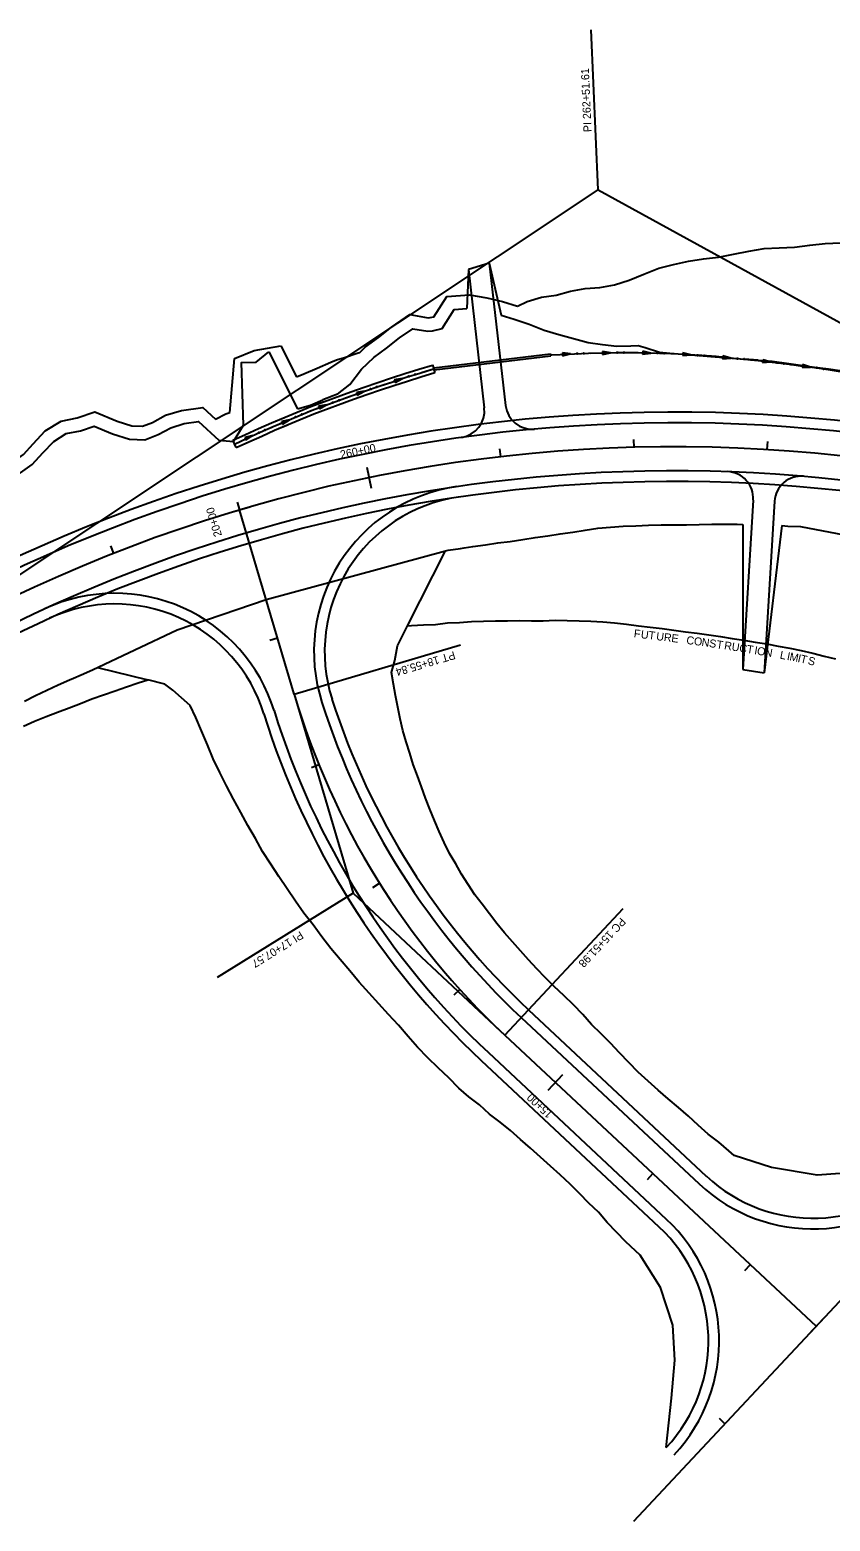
# Model space of a CAD drawing. Extents: x 979959 to 994833, y 1835619 to 1845316.
# Drawn here: x 991264 to 991864, y 1838829 to 1839947 of the extents above; entities that cross this region are included whole.
import ezdxf

# ---------------------------------------------------------------- set-up
doc = ezdxf.new("R2010")
doc.units = 0
for name, color, linetype in [('Future 5 Lane Construction Limits', 7, 'Continuous'), ('R_CONCRETE', 7, 'Continuous'), ('R_Drainage', 7, 'Continuous'), ('R_Horz Alg', 7, 'Continuous'), ('R_Horz Alg Annot', 7, 'Continuous'), ('R_Horz Alg Annot_Side Road', 7, 'Continuous'), ('R_Horz Alg Stationing', 7, 'Continuous'), ('R_Proposed Const Limits', 7, 'Continuous'), ('R_Proposed Road', 7, 'Continuous'), ('R_Proposed Road Future', 7, 'Continuous'), ('R_Special Ditch', 7, 'Continuous')]:
    doc.layers.add(name, color=color, linetype=linetype)

msp = doc.modelspace()

# ---------------------------------------------------------------- linework, layer by layer
msp.add_line((991747.4, 1839704.5), (991781.4, 1839701.9))
for points in [[(991654.7, 1839703.5), (991661.9, 1839703.9), (991672.6, 1839704.4), (991683.2, 1839704.7), (991693.8, 1839705), (991704.4, 1839705.2), (991715.1, 1839705.3), (991720.4, 1839705.3), (991725.7, 1839705.1), (991736.3, 1839704.7), (991746.6, 1839704.6)], [(991781.4, 1839701.9), (991799.7, 1839700.3), (991810.4, 1839699.2)], [(991810.4, 1839699.2), (991820.9, 1839698), (991831.4, 1839696.8), (991835.3, 1839696.3), (991841.9, 1839695.4), (991852.4, 1839694), (991862.8, 1839692.5), (991873.3, 1839690.9), (991883.7, 1839689.2), (991894.1, 1839687.4), (991904.5, 1839685.5), (991910.4, 1839684.4)]]:
    msp.add_lwpolyline(points)
at = {"layer": 'Future 5 Lane Construction Limits'}
for p, q in [((991452.4, 1839710.2), (991464.1, 1839687)), ((991414.3, 1839660.4), (991417.8, 1839700.7))]:
    msp.add_line(p, q, dxfattribs=at)
for points in [[(991630, 1839739.9), (991637.1, 1839743.6), (991647.9, 1839746.7), (991658.8, 1839748.3), (991669.7, 1839751.2), (991680.6, 1839753.3), (991691.7, 1839754.1), (991702.6, 1839755.9), (991713.6, 1839759.4), (991724.6, 1839764), (991735.7, 1839768.4), (991746.9, 1839771.3), (991758.1, 1839773.7), (991769.3, 1839775.4), (991780.6, 1839776.8), (991791.9, 1839779), (991803.3, 1839781.3), (991814.7, 1839783.3), (991826.1, 1839783.7), (991837.5, 1839784.2), (991849, 1839785.7), (991860.5, 1839786.9), (991871.9, 1839787.4)], [(991511.7, 1839705.4), (991515.8, 1839709.2), (991525.7, 1839716.5), (991535.5, 1839724.4), (991549.1, 1839733.7), (991563, 1839731.3), (991564.3, 1839731.4), (991567.1, 1839732.1), (991576.8, 1839747.3), (991594, 1839748.4), (991606.8, 1839746.2), (991618.7, 1839743.4), (991630, 1839739.9)], [(991417.8, 1839700.7), (991432.6, 1839706.9), (991452.4, 1839710.2)], [(991464.1, 1839687), (991469.8, 1839689.2), (991479.8, 1839693.5), (991489.9, 1839698), (991494.2, 1839699.8), (991500.1, 1839701.6), (991510.5, 1839705), (991511.7, 1839705.4)], [(991229, 1839623.7), (991232.5, 1839624.1), (991244.6, 1839626.1), (991254.4, 1839625.2), (991259.5, 1839628.9), (991266.8, 1839636.9), (991275.9, 1839646.5), (991287.9, 1839653.9), (991299.8, 1839656.2), (991313, 1839660.8), (991329.7, 1839653.8), (991340.8, 1839650.4), (991348.8, 1839650), (991356.2, 1839652.9), (991366.1, 1839658.2), (991378, 1839661.8), (991394.1, 1839664), (991403.5, 1839655.4)], [(991403.5, 1839655.4), (991411.3, 1839659.2), (991414.3, 1839660.4)], [(991547.4, 1839500.4), (991550.3, 1839500.6), (991559.4, 1839501.1), (991568.4, 1839501.5), (991577.3, 1839502.6), (991586.3, 1839503), (991595.3, 1839503.7), (991604.3, 1839504), (991613.3, 1839504.2), (991622.3, 1839504.2), (991631.3, 1839504.3), (991640.3, 1839504.1), (991649.2, 1839504.1), (991658.1, 1839504.6), (991667.1, 1839504.5), (991676, 1839504.2), (991684.9, 1839503.9), (991693.8, 1839503.4), (991702.7, 1839502.6), (991711.6, 1839501.6), (991720.5, 1839500.5), (991729.4, 1839499.4), (991738.2, 1839498.3), (991747, 1839497.2), (991755.8, 1839496), (991764.6, 1839494.9), (991773.3, 1839493.6), (991782.1, 1839492.3), (991790.8, 1839491), (991799.5, 1839489.7), (991808.1, 1839488.2), (991816.8, 1839486.8), (991825.4, 1839485.2), (991834.1, 1839483.6), (991842.6, 1839481.9), (991851.2, 1839479.9), (991859.7, 1839477.8), (991868.2, 1839475.7)], [(991259.5, 1839425.2), (991267.9, 1839428.9), (991271.5, 1839430.4), (991276.5, 1839432.4), (991285.1, 1839435.7), (991293.7, 1839439), (991302.4, 1839442.1), (991310.8, 1839445.8), (991319.5, 1839448.8), (991328.2, 1839451.8), (991336.8, 1839454.7), (991336.9, 1839454.8), (991345.6, 1839457.6), (991352.8, 1839460)]]:
    msp.add_lwpolyline(points, dxfattribs=at)
at = {"layer": 'R_CONCRETE'}
for p, q in [((991567.3, 1839693.1), (991566.5, 1839696)), ((991568.2, 1839690.3), (991567.5, 1839692.4)), ((991419, 1839634), (991416.5, 1839639.5))]:
    msp.add_line(p, q, dxfattribs=at)
for points in [[(991474.9, 1839664.9), (991505, 1839675.9), (991515, 1839679.4), (991525.2, 1839682.9), (991535.3, 1839686.3), (991545.5, 1839689.6), (991555.8, 1839692.8), (991566.1, 1839695.9), (991566.5, 1839696)], [(991477.1, 1839659.3), (991507, 1839670.2), (991517, 1839673.8), (991527.1, 1839677.2), (991537.2, 1839680.6), (991547.3, 1839683.9), (991557.5, 1839687), (991567.8, 1839690.2), (991568.2, 1839690.3)], [(991416.5, 1839639.5), (991426.1, 1839643.9), (991435.7, 1839648.2), (991445.5, 1839652.5), (991474.9, 1839664.9)], [(991419, 1839634), (991428.6, 1839638.4), (991438.2, 1839642.7), (991447.8, 1839647), (991477.1, 1839659.3)], [(991426.1, 1839643.9), (991435.7, 1839648.2), (991445.5, 1839652.5), (991455.2, 1839656.6)], [(991428.5, 1839638.4), (991438.2, 1839642.7), (991447.8, 1839647), (991457.6, 1839651.1)]]:
    msp.add_lwpolyline(points, dxfattribs=at)
at = {"layer": 'R_Drainage'}
for p, q in [((991567.2, 1839693.9), (991654.6, 1839704.3)), ((991567.4, 1839692.4), (991654.8, 1839702.8)), ((991654.6, 1839704.3), (991654.8, 1839702.8)), ((991567.2, 1839693.9), (991567.4, 1839692.4))]:
    msp.add_line(p, q, dxfattribs=at)
at = {"layer": 'R_Horz Alg'}
for p, q in [((991462.5, 1839449.1), (991421.5, 1839587.3)), ((991717.1, 1838829.3), (992201.2, 1839346.9))]:
    msp.add_line(p, q, dxfattribs=at)
msp.add_lwpolyline([(991620.4, 1839193.7), (991853.7, 1838975.4)], dxfattribs=at)
for centre, radius, start, end in [((991747.5, 1838488.7), 1145.9, 61.242, 123.6492), ((992011.8, 1839612.1), 573, 196.5251, 226.9104)]:
    msp.add_arc(centre, radius, start, end, dxfattribs=at)
at = {"layer": 'R_Horz Alg Annot'}
for points in [[(991690.3, 1839827.3), (991685.2, 1839947.1)], [(991462.5, 1839449.1), (991587.1, 1839486.1)], [(991506.8, 1839300), (991404.7, 1839236.9)], [(991620.4, 1839193.7), (991709.2, 1839288.6)]]:
    msp.add_lwpolyline(points, dxfattribs=at)
at = {"layer": 'R_Horz Alg Annot_Side Road'}
for p, q in [((991112.5, 1839442.7), (991690.3, 1839827.3)), ((991690.3, 1839827.3), (992298.8, 1839493.3)), ((991462.5, 1839449.1), (991506.8, 1839300)), ((991506.8, 1839300), (991620.4, 1839193.7))]:
    msp.add_line(p, q, dxfattribs=at)
at = {"layer": 'R_Horz Alg Stationing'}
for points in [[(991716.8, 1839640.2), (991717, 1839634.2)], [(991616.5, 1839633.2), (991617.2, 1839627.2)], [(991817.3, 1839638.5), (991816.9, 1839632.5)], [(991516.9, 1839619.4), (991520.1, 1839603.7)], [(991413.8, 1839585), (991429.2, 1839589.6)], [(991419.8, 1839593.1), (991421.5, 1839587.3)], [(991324.8, 1839560.3), (991327, 1839554.7)], [(991444.2, 1839489.7), (991450, 1839491.5)], [(991475.4, 1839394.2), (991481, 1839396.4)], [(991521.4, 1839304.4), (991526.5, 1839307.5)], [(991582.3, 1839223.9), (991586.7, 1839227.9)], [(991652.9, 1839152.3), (991663.8, 1839164)], [(991727.3, 1839085.5), (991731.4, 1839089.8)], [(991800.3, 1839017.1), (991804.4, 1839021.5)], [(991848.3, 1838969.5), (991859.2, 1838981.2)], [(991849.4, 1838979.5), (991853.7, 1838975.4)], [(991781, 1838906.5), (991785.4, 1838902.4)]]:
    msp.add_lwpolyline(points, dxfattribs=at)
at = {"layer": 'R_Proposed Const Limits'}
for p, q in [((991593.1, 1839767.6), (991592, 1839738.3)), ((991608.7, 1839772.3), (991617.6, 1839733.3)), ((991443.5, 1839705.7), (991465, 1839663)), ((991736.3, 1839705.6), (991746.9, 1839704.6)), ((991810.4, 1839699.5), (991799.8, 1839700.4)), ((991494.9, 1839674.1), (991484, 1839669.7)), ((991406, 1839639.5), (991417.1, 1839638.7)), ((991798.8, 1839576.4), (991798.9, 1839467.6)), ((991828.1, 1839575.5), (991814.8, 1839465.3))]:
    msp.add_line(p, q, dxfattribs=at)
for points in [[(991494.9, 1839674.1), (991504.3, 1839681.3), (991512.9, 1839692.8), (991522.1, 1839701.5), (991531.8, 1839708.5), (991541.5, 1839716.3), (991551.4, 1839723.1), (991562.7, 1839721.2), (991566.1, 1839721.6), (991573.4, 1839723.3), (991582.5, 1839737.6), (991592, 1839738.3)], [(991617.6, 1839733.3), (991627.4, 1839730.3), (991638.6, 1839726.4), (991649.8, 1839722.1), (991660.9, 1839718.9), (991671.9, 1839715.8), (991682.8, 1839712.9), (991693.5, 1839711.2), (991704.3, 1839710.1), (991714.9, 1839710.4), (991720.3, 1839710.5), (991725.6, 1839709), (991736.3, 1839705.6)], [(991417.1, 1839638.7), (991424.6, 1839650.8), (991422.9, 1839697.9), (991434.1, 1839698.1), (991443.5, 1839705.7)], [(991746.9, 1839704.6), (991757.5, 1839703.9), (991768.1, 1839703.3), (991778.7, 1839702.5), (991789.3, 1839701.4), (991799.8, 1839700.4)], [(991810.4, 1839699.5), (991820.9, 1839698.7), (991831.4, 1839697.3), (991841.9, 1839695.9), (991852.4, 1839694.3), (991862.9, 1839693), (991873.3, 1839691.5), (991883.8, 1839690.2), (991894.3, 1839689.1), (991904.7, 1839687.6), (991910.8, 1839686.4)], [(991465, 1839663), (991474.8, 1839665.7), (991484, 1839669.7)], [(991220.4, 1839605.2), (991223.8, 1839610.3), (991226.5, 1839613.2), (991233.9, 1839614.2), (991245, 1839616), (991257.2, 1839615), (991266.1, 1839621.3), (991274.1, 1839630), (991282.3, 1839638.6), (991291.6, 1839644.5), (991302.4, 1839646.5), (991312.6, 1839650.1), (991326.3, 1839644.4), (991339, 1839640.4), (991350.5, 1839639.9), (991360.4, 1839643.8), (991369.9, 1839648.9), (991380.1, 1839652), (991390.8, 1839653.5), (991406, 1839639.5)], [(991576, 1839556.7), (991577.8, 1839557.1), (991587.1, 1839558.5), (991590, 1839558.9), (991596.4, 1839559.8), (991605.8, 1839561.1), (991615.1, 1839562.7), (991624.5, 1839563.6), (991633.8, 1839565.1), (991643.2, 1839566.7), (991652.6, 1839567.9), (991661.9, 1839569.4), (991671.3, 1839570.6), (991680.7, 1839572.1), (991690.1, 1839573.5), (991699.6, 1839574.4), (991709, 1839575), (991718.5, 1839575.4), (991723.3, 1839575.6), (991728, 1839575.8), (991737.5, 1839576), (991747, 1839576.1), (991756.5, 1839576.2), (991766, 1839576.4), (991775.5, 1839576.6), (991785, 1839576.6), (991794.5, 1839576.5), (991798.8, 1839576.4)], [(991828.1, 1839575.5), (991832.5, 1839575.2), (991842, 1839574.8), (991907.5, 1839562.5), (992012.3, 1839552.8), (992021.6, 1839550.6), (992030.8, 1839548.2), (992040.2, 1839546.2)], [(991374.8, 1839497.3), (991441.4, 1839520.2), (991576, 1839556.7)], [(991547.4, 1839500.4), (991576, 1839556.7)], [(991260.2, 1839443.9), (991268.6, 1839448.2), (991277, 1839452.1), (991285.5, 1839456.2), (991294.1, 1839459.9), (991297, 1839461.1), (991302.7, 1839463.6), (991311.2, 1839467.5), (991374.8, 1839497.3)], [(991535.4, 1839465.4), (991537.8, 1839474.4), (991539.8, 1839485.4), (991547.4, 1839500.4)], [(991315, 1839469.3), (991352.8, 1839460)], [(991720.4, 1839165.9), (991713.3, 1839173), (991706.4, 1839180.3), (991699.5, 1839187.5), (991692.5, 1839194.6), (991685.3, 1839201.6), (991678.8, 1839209.2), (991671.8, 1839216.4), (991664.6, 1839223.4), (991657.3, 1839230.2), (991650.7, 1839236.8), (991644.4, 1839243.3), (991638.2, 1839250), (991632.1, 1839256.7), (991626.2, 1839263.6), (991620.2, 1839270.4), (991614.5, 1839277.4), (991609, 1839284.6), (991603.5, 1839291.8), (991597.9, 1839298.9), (991592.9, 1839306.5), (991588, 1839314.2), (991583.6, 1839322), (991578.9, 1839329.8), (991575, 1839338), (991571.2, 1839346.2), (991567.6, 1839354.5), (991564.2, 1839362.9), (991561, 1839371.3), (991558, 1839379.8), (991554.9, 1839388.1), (991551.7, 1839396.5), (991549.1, 1839405), (991546.4, 1839413.5), (991543.8, 1839422), (991541.8, 1839430.7), (991540.1, 1839439.4), (991538.5, 1839448.1), (991537, 1839456.8), (991535.4, 1839465.4)], [(991384.6, 1839440.8), (991371.4, 1839452.3), (991365.4, 1839456.8), (991352.8, 1839460)], [(991669.3, 1839082), (991661.9, 1839088.8), (991654.5, 1839095.5), (991647.1, 1839102.2), (991639.6, 1839108.9), (991632.1, 1839115.5), (991624.6, 1839122.1), (991616.8, 1839128.4), (991608.8, 1839134.4), (991601.5, 1839141.3), (991593.4, 1839147.3), (991586, 1839154), (991578.5, 1839161.7), (991570.5, 1839169.1), (991562.6, 1839176.6), (991555, 1839184.5), (991547.8, 1839192.7), (991540.7, 1839201), (991533.3, 1839209), (991525.9, 1839217), (991518.6, 1839225.2), (991511.2, 1839233.4), (991504.2, 1839241.8), (991497, 1839250.2), (991489.9, 1839258.6), (991483.2, 1839267.3), (991476.6, 1839276.2), (991469.8, 1839285), (991463.4, 1839294.1), (991457.1, 1839303.2), (991450.9, 1839312.5), (991444.9, 1839321.9), (991438.8, 1839331.3), (991433.4, 1839341), (991427.8, 1839350.7), (991422.4, 1839360.6), (991417, 1839370.5), (991411.8, 1839380.5), (991406.7, 1839390.5), (991401.8, 1839400.7), (991397.5, 1839411.2), (991393.1, 1839421.6), (991388.8, 1839431.6), (991384.6, 1839440.8)], [(991936.8, 1839093.5), (991889.1, 1839091.2), (991854.5, 1839088.6), (991820.2, 1839094.5), (991792.2, 1839103.4), (991788.4, 1839106.8), (991780.8, 1839113.4), (991772.7, 1839119.4), (991765.3, 1839126.1), (991758, 1839132.9), (991750.5, 1839139.5), (991742.8, 1839145.9), (991735.2, 1839152.5), (991727.8, 1839159.2), (991720.4, 1839165.9)], [(991741.4, 1838884.6), (991745.3, 1838921.6), (991747.8, 1838950), (991746.2, 1838976.3), (991737, 1839004.4), (991721.9, 1839028.6), (991718.3, 1839031.9), (991711, 1839038.8), (991704, 1839045.9), (991697.2, 1839053.3), (991690.6, 1839060.9), (991683.4, 1839067.8), (991676.4, 1839075), (991669.3, 1839082)]]:
    msp.add_lwpolyline(points, dxfattribs=at)
at = {"layer": 'R_Proposed Road'}
for p, q in [((991608.7, 1839772.3), (991593.1, 1839767.6)), ((991798.9, 1839467.6), (991814.8, 1839465.3))]:
    msp.add_line(p, q, dxfattribs=at)
for points in [[(991593.1, 1839767.6), (991605, 1839663.7)], [(991608.7, 1839772.3), (991620.9, 1839665.6)], [(991806.6, 1839594.7), (991798.9, 1839467.6)], [(991822.6, 1839593.8), (991814.8, 1839465.3)]]:
    msp.add_lwpolyline(points, dxfattribs=at)
for centre, radius, start, end in [((991585.1, 1839661.5), 20, 277.8803, 6.5251), ((991640.8, 1839667.8), 20, 186.5251, 275.1699), ((991747.5, 1838488.7), 1171.9, 67.297, 123.6492), ((991747.5, 1838488.7), 1163.9, 67.297, 123.6492), ((991747.5, 1838488.7), 1127.9, 70.2062, 123.6492), ((991747.5, 1838488.7), 1119.9, 70.2062, 123.6492), ((991786.6, 1839596), 20, 356.5251, 87.9732), ((991842.5, 1839592.6), 20, 85.0769, 176.5251)]:
    msp.add_arc(centre, radius, start, end, dxfattribs=at)
at = {"layer": 'R_Proposed Road Future'}
for points in [[(991632.7, 1839206.8), (991766, 1839082.1)], [(991638.2, 1839212.6), (991771.4, 1839088)], [(991602.6, 1839174.7), (991735.9, 1839050)], [(991608.1, 1839180.5), (991741.4, 1839055.8)]]:
    msp.add_lwpolyline(points, dxfattribs=at)
for centre, radius, start, end in [((991602.3, 1839481.1), 125, 98.3221, 197.7376), ((991602.3, 1839481.1), 117, 98.3221, 197.7376), ((991328.1, 1839399.8), 125, 17.2514, 114.7192), ((991328.1, 1839399.8), 117, 17.2514, 114.7192), ((992011.8, 1839612.1), 555, 197.7376, 226.9104), ((992011.8, 1839612.1), 547, 197.7376, 226.9104), ((992011.8, 1839612.1), 599, 197.2514, 226.9104), ((992011.8, 1839612.1), 591, 197.2514, 226.9104), ((991851.4, 1839173.4), 117, 226.9104, 316.9104), ((991851.4, 1839173.4), 125, 226.9104, 316.9104), ((991656, 1838964.5), 117, 316.9104, 46.9104), ((991656, 1838964.5), 125, 316.9104, 46.9104)]:
    msp.add_arc(centre, radius, start, end, dxfattribs=at)
at = {"layer": 'R_Special Ditch'}
for p, q in [((991669.7, 1839704.2), (991663.7, 1839705)), ((991663.7, 1839705), (991663.7, 1839702.9)), ((991663.7, 1839702.9), (991669.7, 1839704.2)), ((991699.7, 1839705.1), (991693.7, 1839706.1)), ((991693.7, 1839706.1), (991693.7, 1839703.9)), ((991693.7, 1839703.9), (991699.7, 1839705.1)), ((991723.8, 1839706.2), (991723.7, 1839704.1)), ((991723.7, 1839704.1), (991729.8, 1839704.9)), ((991729.8, 1839704.9), (991723.8, 1839706.2)), ((991746.6, 1839704.6), (991747.4, 1839704.5)), ((991753.8, 1839705.1), (991753.7, 1839703)), ((991753.7, 1839703), (991759.7, 1839703.6)), ((991759.7, 1839703.6), (991753.8, 1839705.1)), ((991783.8, 1839702.7), (991783.6, 1839700.6)), ((991783.6, 1839700.6), (991789.7, 1839701.1)), ((991789.7, 1839701.1), (991783.8, 1839702.7)), ((991813.7, 1839699.9), (991813.5, 1839697.8)), ((991813.5, 1839697.8), (991819.6, 1839698.2)), ((991819.6, 1839698.2), (991813.7, 1839699.9)), ((991843.6, 1839696.3), (991843.3, 1839694.2)), ((991849.4, 1839694.4), (991843.6, 1839696.3)), ((991543.6, 1839685.8), (991537.5, 1839684.9)), ((991537.5, 1839684.9), (991538.2, 1839682.9)), ((991538.2, 1839682.9), (991543.6, 1839685.8)), ((991843.3, 1839694.2), (991849.4, 1839694.4)), ((991515.1, 1839676.3), (991509.1, 1839675.3)), ((991509.1, 1839675.3), (991509.8, 1839673.3)), ((991509.8, 1839673.3), (991515.1, 1839676.3)), ((991486.8, 1839666.1), (991480.8, 1839665)), ((991480.8, 1839665), (991481.5, 1839663)), ((991481.5, 1839663), (991486.8, 1839666.1)), ((991458.9, 1839654.9), (991453, 1839653.5)), ((991453, 1839653.5), (991453.8, 1839651.6)), ((991453.8, 1839651.6), (991458.9, 1839654.9)), ((991431.4, 1839643), (991425.5, 1839641.5)), ((991425.5, 1839641.5), (991426.3, 1839639.6)), ((991426.3, 1839639.6), (991431.4, 1839643))]:
    msp.add_line(p, q, dxfattribs=at)
for points in [[(991654.7, 1839703.5), (991661.9, 1839703.9), (991669.7, 1839704.2)], [(991684.7, 1839704.8), (991693.8, 1839705), (991699.7, 1839705.1)], [(991684.7, 1839704.8), (991684.7, 1839704.8)], [(991714.7, 1839705.3), (991714.8, 1839705.3)], [(991714.8, 1839705.3), (991715.1, 1839705.3), (991720.4, 1839705.3), (991725.7, 1839705.1), (991729.8, 1839704.9)], [(991744.7, 1839704.6), (991744.8, 1839704.6)], [(991744.8, 1839704.6), (991746.6, 1839704.6), (991747.4, 1839704.5), (991759.7, 1839703.6)], [(991774.7, 1839702.4), (991781.4, 1839701.9), (991789.7, 1839701.1)], [(991774.7, 1839702.4), (991774.7, 1839702.4)], [(991804.6, 1839699.8), (991804.7, 1839699.8)], [(991804.7, 1839699.8), (991810.4, 1839699.2), (991819.6, 1839698.2)], [(991834.5, 1839696.4), (991835.3, 1839696.3), (991841.9, 1839695.4), (991849.4, 1839694.4)], [(991834.5, 1839696.4), (991834.5, 1839696.4)], [(991476, 1839662.1), (991506, 1839673), (991516, 1839676.6), (991526.1, 1839680), (991536.3, 1839683.4), (991546.4, 1839686.7), (991556.7, 1839689.9), (991566.9, 1839693), (991567.3, 1839693.1)], [(991529.3, 1839681.1), (991536.3, 1839683.4), (991543.6, 1839685.8)], [(991557.9, 1839690.3), (991566.9, 1839693), (991567.3, 1839693.1)], [(991557.9, 1839690.3), (991557.9, 1839690.3)], [(991864.2, 1839692.3), (991864.3, 1839692.3)], [(991500.9, 1839671.2), (991506, 1839673), (991515.1, 1839676.3)], [(991529.3, 1839681.1), (991529.3, 1839681.1)], [(991472.8, 1839660.8), (991476, 1839662.1), (991486.8, 1839666.1)], [(991500.9, 1839671.2), (991500.9, 1839671.2)], [(991417.7, 1839636.7), (991427.3, 1839641.2), (991437, 1839645.5), (991446.7, 1839649.7), (991476, 1839662.1)], [(991445.1, 1839649), (991446.7, 1839649.7), (991458.9, 1839654.9)], [(991472.7, 1839660.8), (991472.8, 1839660.8)], [(991417.7, 1839636.7), (991427.3, 1839641.2), (991431.4, 1839643)], [(991445.1, 1839649), (991445.1, 1839649)]]:
    msp.add_lwpolyline(points, dxfattribs=at)
for centre in [(991674.7, 1839704.5), (991679.7, 1839704.6), (991704.7, 1839705.2), (991709.7, 1839705.2), (991734.8, 1839704.8), (991739.8, 1839704.7), (991764.7, 1839703.2), (991769.7, 1839702.8), (991794.7, 1839700.7), (991799.7, 1839700.3), (991824.6, 1839697.6), (991829.5, 1839697), (991548.3, 1839687.3), (991553.1, 1839688.8), (991854.3, 1839693.8), (991859.3, 1839693), (991519.8, 1839677.9), (991524.5, 1839679.5), (991491.5, 1839667.8), (991496.2, 1839669.5), (991463.5, 1839656.9), (991468.1, 1839658.9), (991435.9, 1839645.1), (991440.5, 1839647.1)]:
    msp.add_circle(centre, 0.375, dxfattribs=at)

# ---------------------------------------------------------------- texts
at = {"layer": 'Future 5 Lane Construction Limits'}
for s, rotation, p in [('F', 353.0299, (991716.8, 1839491.9)), ('U', 353.2441, (991722.1, 1839491.2)), ('T', 352.9315, (991727.8, 1839490.6)), ('U', 352.9315, (991733.6, 1839489.8)), ('R', 352.5816, (991739.3, 1839489.1)), ('E', 352.5432, (991744.9, 1839488.4)), ('C', 352.3799, (991756.2, 1839486.9)), ('O', 351.9802, (991761.8, 1839486.2)), ('N', 351.9802, (991767.6, 1839485.4)), ('S', 351.5809, (991773.2, 1839484.6)), ('T', 351.4081, (991778.7, 1839483.7)), ('R', 351.4081, (991784.5, 1839482.9)), ('U', 351.057, (991790.1, 1839482)), ('C', 350.664, (991795.8, 1839481.1)), ('T', 350.664, (991801.4, 1839480.2)), ('I', 350.3314, (991807.1, 1839479.3)), ('O', 350.3314, (991809.1, 1839478.9)), ('N', 350.0123, (991814.8, 1839478)), ('L', 349.2853, (991826.2, 1839475.9)), ('I', 348.883, (991831.5, 1839474.9)), ('M', 348.883, (991833.4, 1839474.6)), ('I', 346.891, (991839.5, 1839473.4)), ('T', 346.891, (991841.5, 1839473)), ('S', 346.227, (991847.1, 1839471.7))]:
    msp.add_text(s, height=6, rotation=rotation, dxfattribs=at).set_placement(p)
at = {"layer": 'R_Horz Alg Annot'}
for s, rotation, p in [('PI 262+51.61', 92.4456, (991685.4, 1839870.6)), ('PT 18+55.84', 196.5251, (991582.2, 1839481.5)), ('PI 17+07.57', 211.7177, (991467, 1839271.8)), ('PC 15+51.98', 226.9104, (991707.3, 1839282.2))]:
    msp.add_text(s, height=6, rotation=rotation, dxfattribs=at).set_placement(p)
at = {"layer": 'R_Horz Alg Stationing'}
for s, rotation, p in [('260+00', 11.5251, (991497.6, 1839625.7)), ('20+00', 106.5251, (991408.4, 1839568.2)), ('15+00', 136.9104, (991656.8, 1839135))]:
    msp.add_text(s, height=6, rotation=rotation, dxfattribs=at).set_placement(p)

doc.saveas('drawing.dxf')
